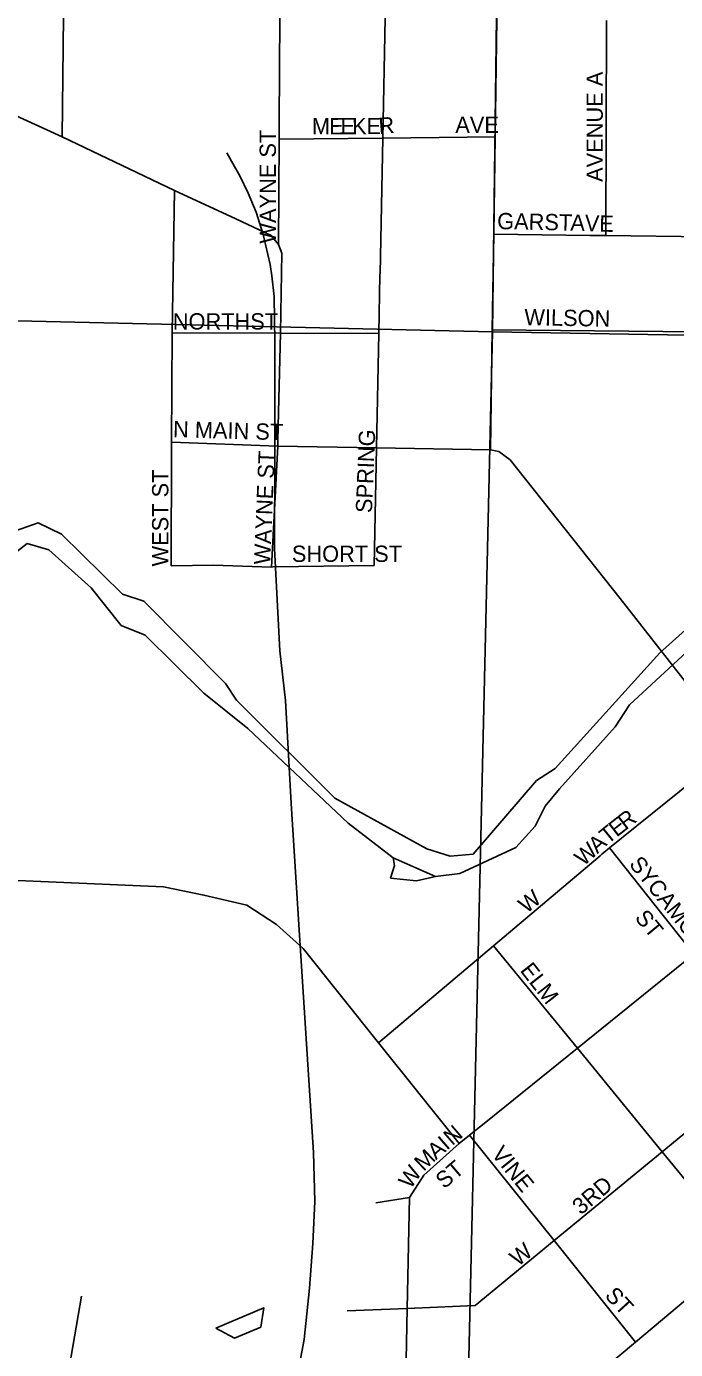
# Model space of a CAD drawing. Extents: x -784 to 1375, y -225 to 440.
# Drawn here: x 287.9 to 295.68, y 352.51 to 368.36 of the extents above; entities that cross this region are included whole.
import ezdxf

# ---------------------------------------------------------------- set-up
doc = ezdxf.new("R2010")
doc.units = 0
for name, color, linetype in [('GM_X_City_Street', 7, 'Continuous'), ('GM_X_City_Street_Text', 7, 'Continuous'), ('GM_X_Major_River', 7, 'Continuous'), ('GM_X_Minor_Lake', 7, 'Continuous'), ('GM_X_Minor_River', 7, 'Continuous'), ('GM_X_Rail_Line', 7, 'Continuous'), ('GM_X_Section', 7, 'Continuous'), ('GM_X_State_Route', 7, 'Continuous')]:
    doc.layers.add(name, color=color, linetype=linetype)

msp = doc.modelspace()

# ---------------------------------------------------------------- linework, layer by layer
at = {"layer": 'GM_X_City_Street'}
for points in [[(290.927, 367.203), (290.935, 368.472), (290.945, 369.949)], [(292.135, 365.382), (292.136, 365.399), (292.169, 367.021), (292.198, 368.458), (292.227, 369.927)], [(294.841, 365.852), (294.85, 368.429)], [(290.918, 365.746), (290.926, 367.007), (290.927, 367.147), (290.927, 367.203)], [(290.926, 367.007), (292.169, 367.021), (293.516, 367.037)], [(293.48, 364.725), (297.983, 364.681), (298.126, 364.747), (298.217, 364.916), (298.222, 366.312), (298.27, 366.488), (298.293, 366.571), (298.294, 366.575)], [(294.649, 365.855), (294.701, 365.854), (294.841, 365.852), (296.046, 365.838), (297.267, 365.824), (297.503, 365.848), (297.679, 365.968), (297.871, 366.126), (298.27, 366.488)], [(289.638, 363.291), (289.638, 363.379), (289.645, 364.686), (289.673, 366.393)], [(293.498, 365.868), (294.649, 365.855)], [(292.065, 361.899), (292.094, 363.309), (292.121, 364.68), (292.135, 365.382)], [(289.645, 364.686), (290.945, 364.683), (292.121, 364.68)], [(289.631, 361.896), (289.638, 363.291)], [(289.638, 363.379), (290.912, 363.331)], [(290.836, 361.882), (290.912, 363.331)], [(289.631, 361.896), (290.14, 361.904), (290.836, 361.882)], [(290.836, 361.882), (290.856, 361.883), (292.065, 361.899)], [(294.796, 358.441), (294.886, 358.517), (296.399, 359.735)], [(295.898, 357.244), (294.886, 358.517)], [(292.119, 356.183), (293.494, 357.343), (294.774, 358.423), (294.796, 358.441)], [(296.496, 353.687), (295.518, 354.877), (294.501, 356.117), (293.494, 357.343)], [(292.554, 353.006), (293.277, 353.035), (294.223, 353.813), (295.518, 354.877), (296.891, 356.006), (296.958, 356.06), (296.96, 356.062)], [(293.82, 351.442), (294.658, 352.146), (295.198, 352.598), (296.496, 353.687), (296.611, 353.783), (297.844, 354.818), (299.354, 356.01)], [(295.198, 352.598), (294.223, 353.813), (293.209, 355.076)], [(292.49, 354.328), (292.66, 354.599), (293.085, 354.976)], [(292.086, 354.264), (292.49, 354.328)], [(292.36, 347.981), (292.36, 347.982), (292.404, 350.122), (292.463, 353.002), (292.49, 354.328)], [(291.741, 352.973), (292.463, 353.002), (292.549, 353.006), (292.554, 353.006)]]:
    msp.add_lwpolyline(points, dxfattribs=at)
at = {"layer": 'GM_X_Major_River'}
msp.add_line((292.293, 358.399), (292.8, 358.173), dxfattribs=at)
for points in [[(292.8, 358.173), (293.092, 358.211), (293.764, 358.521), (293.996, 358.776), (294.117, 359.017), (294.285, 359.226), (294.956, 359.968), (295.125, 360.231), (296.495, 361.495), (297.552, 362.339), (298.246, 363.041), (298.855, 363.854), (298.868, 366.026), (298.982, 366.746), (299.277, 367.031), (299.902, 367.358), (300.173, 367.612), (300.876, 367.906), (301.819, 368.071), (305.39, 368.317), (305.648, 368.32), (306.4, 368.292), (306.666, 368.209), (306.797, 368.034)], [(296.698, 361.938), (295.489, 360.853), (294.235, 359.47), (294.013, 359.325), (293.253, 358.444), (292.978, 358.417), (292.698, 358.508), (291.595, 359.114), (290.415, 360.287), (290.285, 360.485), (289.307, 361.473), (289.049, 361.556), (288.317, 362.274), (288.037, 362.412), (287.769, 362.315)], [(287.278, 361.675), (287.907, 362.163), (288.165, 362.088), (288.674, 361.633), (289.035, 361.18), (289.323, 361.065), (290.025, 360.372), (290.551, 359.947), (291.754, 358.814), (292.293, 358.399)], [(292.8, 358.173), (292.293, 358.399), (292.308, 358.305), (292.26, 358.154)], [(292.26, 358.154), (292.572, 358.121), (292.8, 358.173)]]:
    msp.add_lwpolyline(points, dxfattribs=at)
at = {"layer": 'GM_X_Minor_Lake'}
for points in [[(290.708, 352.775), (290.742, 353.01), (290.168, 352.766)], [(290.168, 352.766), (290.393, 352.646), (290.708, 352.775)]]:
    msp.add_lwpolyline(points, dxfattribs=at)
at = {"layer": 'GM_X_Minor_River'}
msp.add_lwpolyline([(288.558, 353.149), (288.058, 350.249), (288.753, 348.693), (289.169, 348.231), (288.902, 347.742), (288.243, 346.812), (288.118, 344.955), (288.262, 344.678), (288.281, 344.403), (286.703, 341.975), (278.796, 325.615), (278.65, 325.382)], dxfattribs=at)
at = {"layer": 'GM_X_Rail_Line'}
for points in [[(290.392, 366.68), (290.299, 366.844)], [(290.876, 363.302), (290.876, 364.576), (290.867, 365.123), (290.84, 365.371), (290.819, 365.506), (290.735, 365.864), (290.652, 366.133), (290.556, 366.36), (290.454, 366.569), (290.392, 366.68)], [(290.876, 363.223), (290.876, 363.302)], [(287.84, 346.697), (289.019, 348.383), (289.811, 349.528), (290.134, 349.979), (290.402, 350.384), (290.641, 350.797), (290.824, 351.192), (290.947, 351.52), (291.066, 351.89), (291.156, 352.248), (291.228, 352.627), (291.292, 353.244), (291.33, 353.78), (291.356, 354.283), (291.339, 354.87), (291.22, 356.73), (291.169, 357.471), (291.071, 359.05), (291.003, 360.284), (290.936, 360.877), (290.873, 362.102), (290.876, 363.223)]]:
    msp.add_lwpolyline(points, dxfattribs=at)
at = {"layer": 'GM_X_Section'}
for points in [[(273.043, 385.919), (293.747, 385.447), (293.485, 364.699), (272.601, 365.183)], [(293.747, 385.447), (314.846, 385.028), (314.451, 364.338), (293.485, 364.699)], [(272.601, 365.183), (293.485, 364.699), (293.008, 344.097), (292.781, 344.102), (272.386, 344.418)], [(293.485, 364.699), (314.451, 364.338), (313.882, 343.598), (293.008, 344.097)]]:
    msp.add_lwpolyline(points, close=True, dxfattribs=at)
at = {"layer": 'GM_X_State_Route'}
for points in [[(293.458, 363.284), (293.48, 364.725), (293.498, 365.868), (293.516, 367.037), (293.537, 368.444), (293.56, 369.904), (293.59, 371.864), (293.591, 371.947)], [(288.325, 367.035), (288.351, 369.202), (288.359, 369.895), (288.36, 369.993), (288.361, 370.023)], [(286.23, 367.988), (286.416, 367.904), (288.325, 367.035)], [(290.407, 366.053), (289.673, 366.393), (288.325, 367.035)], [(290.921, 363.735), (290.945, 364.683), (290.958, 365.641), (290.918, 365.746), (290.832, 365.855), (290.689, 365.923), (290.407, 366.053)], [(293.458, 363.284), (292.094, 363.309), (290.912, 363.331), (290.912, 363.392), (290.921, 363.735)], [(297.388, 358.445), (296.399, 359.735), (295.013, 361.506), (293.695, 363.164), (293.561, 363.265), (293.458, 363.284)], [(293.404, 355.233), (294.501, 356.117), (295.898, 357.244), (297.388, 358.445)], [(286.873, 358.165), (289.542, 358.05), (290.025, 357.952), (290.539, 357.83), (290.894, 357.601), (291.216, 357.311), (292.119, 356.183), (293.085, 354.976), (293.209, 355.076), (293.329, 355.173), (293.404, 355.233)]]:
    msp.add_lwpolyline(points, dxfattribs=at)

# ---------------------------------------------------------------- texts
at = {"layer": 'GM_X_City_Street_Text'}
for s, height, rotation, p in [('AVENUE A', 0.1953, 90, (294.806, 366.495)), ('M', 0.195, 0.1821, (291.32, 367.065)), ('E', 0.195, 0.1882, (291.526, 367.065)), ('E', 0.195, 0.1882, (291.664, 367.066)), ('K', 0.195, 0.1906, (291.801, 367.066)), ('E', 0.195, 0.1912, (291.973, 367.067)), ('R', 0.195, 4.5268, (292.126, 367.068)), ('AVE', 0.1953, 0, (293.038, 367.082)), ('WAYNE ST', 0.1953, 90, (290.888, 365.756)), ('GARST', 0.1953, 358.7553, (293.538, 365.93)), ('A', 0.195, 357.7919, (294.415, 365.913)), ('V', 0.195, 357.7888, (294.587, 365.907)), ('E', 0.195, 358.5566, (294.761, 365.9)), ('NORTH', 0.1953, 0, (289.652, 364.727)), ('ST', 0.1953, 0, (290.581, 364.727)), ('WILSON', 0.1953, 358.9397, (293.864, 364.779)), ('N MAIN ST', 0.1953, 358.3612, (289.653, 363.438)), ('SPRING', 0.1953, 87.6628, (292.039, 362.526)), ('WAYNE ST', 0.1953, 87.581, (290.819, 361.908)), ('WEST ST', 0.1953, 90, (289.599, 361.889)), ('SHORT ST', 0.1953, 0, (291.079, 361.943)), ('E', 0.195, 38.0325, (294.972, 358.64)), ('R', 0.195, 37.9884, (295.08, 358.725)), ('T', 0.195, 38.8689, (294.865, 358.554)), ('W', 0.195, 43.0705, (294.577, 358.289)), ('A', 0.195, 42.1164, (294.74, 358.441)), ('SYCAMORE', 0.1953, 308.6594, (295.112, 358.32)), ('W', 0.195, 38.6571, (293.892, 357.724)), ('ST', 0.1953, 309.8038, (295.18, 357.676)), ('ELM', 0.1953, 308.0479, (293.806, 357.048)), ('N', 0.195, 40.7607, (293.001, 354.944)), ('I', 0.195, 40.7607, (292.936, 354.888)), ('M', 0.195, 43.5115, (292.658, 354.635)), ('A', 0.195, 40.7607, (292.806, 354.775)), ('VINE', 0.1953, 308.9264, (293.462, 354.848)), ('W', 0.195, 54.5144, (292.501, 354.422)), ('ST', 0.1953, 40.2414, (292.905, 354.425)), ('3RD', 0.1953, 40.3674, (294.544, 354.114)), ('W', 0.195, 38.6571, (293.789, 353.496)), ('ST', 0.1953, 312.5162, (294.819, 353.148))]:
    msp.add_text(s, height=height, rotation=rotation, dxfattribs=at).set_placement(p)

doc.saveas('drawing.dxf')
